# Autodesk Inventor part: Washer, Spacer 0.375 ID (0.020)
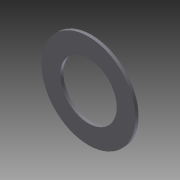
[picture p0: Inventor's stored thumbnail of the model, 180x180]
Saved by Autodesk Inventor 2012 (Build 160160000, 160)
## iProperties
Created: 2012-08
Part Number: Washer, Spacer 0.375 ID (0.020)
Material: Steel
Document SubType Name: Modeling
Designer: Owner
Mass: 0.505162 g
Surface Area: 2.9389 cm^2
Volume: 0.0643518 cm^3
Density: 7.85 g/cm^3
Author: Owner
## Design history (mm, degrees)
sketch "Sketch1"
  geometry: C1 r 4.763 at (0, 0); C2 r 7.938 at (0, 0); 1 further point
  constraints: 2 centre point, 2 coincident
  dimensions: "d0" = 9.525 diameter of C1; "d1" = 15.875 diameter of C2
extrude "Extrusion1" new body sketch "Sketch1" stored distance "d2" = 0.508; taper "d3" = 0 deg
body "Solid1"
